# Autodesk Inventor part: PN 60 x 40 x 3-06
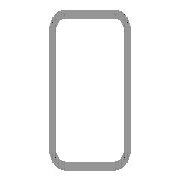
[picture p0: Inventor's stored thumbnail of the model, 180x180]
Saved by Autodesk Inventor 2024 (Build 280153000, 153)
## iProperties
Company: ATC
IsCustomPart: 1
_CCFamilyMember: 10
_CCFamilyDisplayName: PN EN 10219-2 (Profil walcowany, prostokątny - kształtowany na zimno) - Konstrukcyjne profile wydrążone ze stali węglowej i drobnoziarnistej, spawane, kształtow
_FrameMemberDoc: Frame Member File
_Version: 15.0.0
Created: 2023-03
Part Number: PN 60 x 40 x 3-06
Material: Ogólny
Description: Konstrukcyjne profile wydrążone ze stali węglowej i drobnoziarnistej, spawane, kształtowane na zimno
Document SubType Name: Modeling
Standard: PN EN 10219-2
Designer: Andrzej Jaskulski
Standards Organization: PN
Language: pl-PL
Size Designation: 60 x 40 x 3
Categories: <MemberInstance><Categories><Category DisplayName="Kształtowniki konstrukcyjne" InternalName="089c4875-fa83-4c05-b084-43b9cc11f5ed" Mnemonic="GRDR"><CategoryPar
Stock Number: 60 x 40 x 3
Density: 1 g/cm^3
Appearance: Domyślna
Checked By: A.J.
Engr Approved By: Andrzej Jaskulski
Mfg Approved By: Andrzej Jaskulski
Authority: A.J.
G_L: 240,000 mm
G_W: 40,000 mm
G_H: 60,000 mm
+302763FE-E428-4782-AB0C-9204278D63AD+CUTDETAIL1: Połączenie narożne
+7DCE26F0-1766-46EF-813B-A8C94F2840FD+CUTDETAIL2: Połączenie narożne
Author: Andrzej Jaskulski
Title: A.J.: Kurs R2024-MEP
Revision Number: 1/24
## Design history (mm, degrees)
node "Płaszczyzna początkowa"
node "Płaszczyzna końcowa"
sketch "Szkic"
  geometry: L1 (-20, -24)-(-20, 24); L2 (-14, 30)-(14, 30); L3 (20, 24)-(20, -24); L4 (14, -30)-(-14, -30); L5 (-14, 27)-(14, 27); L6 (17, 24)-(17, -24); L7 (14, -27)-(-14, -27); L8 (-17, -24)-(-17, 24); L9 (0, 43.74)-(0, -43.74) reference; L10 (-29.74, 0)-(29.74, 0) reference; A1 r 6 centre (-14, -24) between (-20, -24) and (-14, -30); A2 r 6 centre (-14, 24) between (-14, 30) and (-20, 24); A3 r 6 centre (14, 24) between (20, 24) and (14, 30); A4 r 6 centre (14, -24) between (14, -30) and (20, -24); A5 r 3 centre (-14, 24) between (-14, 27) and (-17, 24); A6 r 3 centre (14, 24) between (17, 24) and (14, 27); A7 r 3 centre (14, -24) between (14, -27) and (17, -24); A8 r 3 centre (-14, -24) between (-17, -24) and (-14, -27)
  constraints: 16 end point, 16 point on circle, 8 centre point, 8 tangent, 4 parallel, 3 equal radius, 2 perpendicular, 7 other
  dimensions: "d7" = 6 radius of A1 (= G_IR); "d10" = 60 distance between parallel lines of L2 L4 (= G_H); "d11" = 40 distance between parallel lines of L1 L3 (= G_W); "d12" = 3 distance between parallel lines of L3 L6 (= G_T); "d15" = 30 distance between parallel lines of L2 L10 (= 0.5 x d10); "d16" = 20 distance between parallel lines of L9 L3 (= 0.5 x d11)
extrude "Bryła" new body sketch "Szkic" stored distance "d3" = 240 (= G_L); taper "d4" = 0 deg
node "Driven Length"
  sketch "Sketch3"
    geometry: L1 (0, 0)-(10, 0) reference
    constraints: 2 end point, 1 horizontal
  workplane "Work Plane3"
node "Płaszczyzna konstrukcyjna4"
feature "Podział1"
node "Płaszczyzna konstrukcyjna5"
feature "Podział2"
node "Otwory1"
node "Otwory2"
body "Solid1"
sketch "Sketch4"
  geometry: L1 (-2, 0)-(12, 0) reference; L2 (-2, 240)-(12, 240) reference
  dimensions: "d18" = 240 distance between parallel lines of L1 L2 (derived)
sketch "Szkic5"
  geometry: 1 further point
hole "Otwór1" sketch "Szkic5" diameter "d19" = 22; stored, may be unused: countersink angle "d23" = 90 deg, drill point angle "d25" = 0 deg; dims "d20" = 6, "d21" = 4, "d22" = 2, "d24" = 8
sketch "Szkic6"
  geometry: 1 further point
hole "Otwór2" sketch "Szkic6" diameter "d26" = 22; stored, may be unused: countersink angle "d30" = 90 deg, drill point angle "d32" = 0 deg; dims "d27" = 6, "d28" = 4, "d29" = 2, "d31" = 8
other parameters: "G_W" = 40 [user parameter; used in 1 equation term], "G_H" = 60 [user parameter; used in 1 equation term], "G_T" = 3 [user parameter; used in 1 equation term], "G_IR" = 6 [user parameter; used in 1 equation term], "G_L" = 240 (= d18) [user parameter; used in 1 equation term], "G_OFFSET_START" = 0 [user parameter; used in 1 equation term], "G_OFFSET_END" = 0 [user parameter; used in 1 equation term], "d13" = 0 (computed from G_OFFSET_START), "d17" = 90 deg
